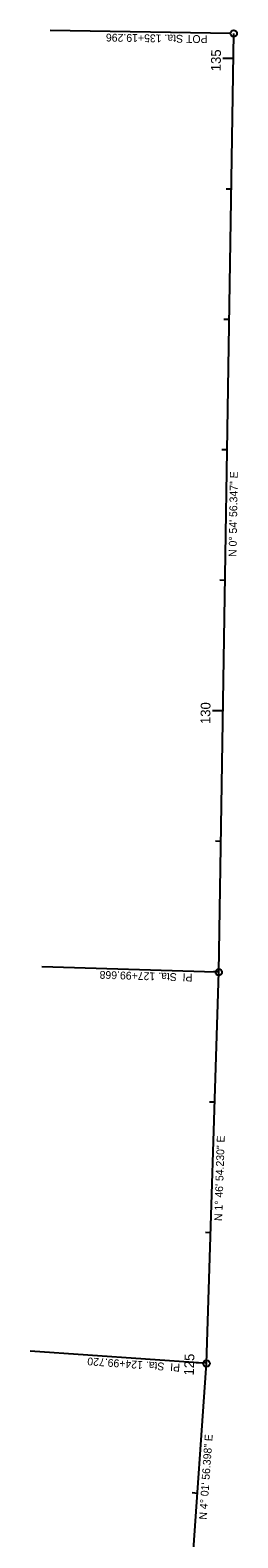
# Model space of a CAD drawing. Extents: x 1384921 to 1386651, y 1973711 to 1976329.
# Drawn here: x 1385069 to 1385228, y 1975173 to 1976329 of the extents above; entities that cross this region are included whole.
import ezdxf

# ---------------------------------------------------------------- set-up
doc = ezdxf.new("R2010")
doc.units = 0
for name, color, linetype in [('S_BREAKLINE', 7, 'Continuous'), ('S_BRIDGE', 7, 'Continuous'), ('S_DRIVEWAY', 7, 'Continuous'), ('S_PAVEMENT_CROWN', 7, 'Continuous'), ('S_SHOULDER', 7, 'Continuous')]:
    doc.layers.add(name, color=color, linetype=linetype)

msp = doc.modelspace()

# ---------------------------------------------------------------- linework, layer by layer
at = {"layer": 'S_BREAKLINE'}
for p, q in [((1385222.8, 1976326.3), (1385084.6, 1976328.5)), ((1385211.3, 1975606.8), (1385078.4, 1975610.9)), ((1385202, 1975307.1), (1385069.4, 1975316.4))]:
    msp.add_line(p, q, dxfattribs=at)
for centre in [(1385225.3, 1976326.2), (1385213.8, 1975606.7), (1385204.5, 1975306.9)]:
    msp.add_circle(centre, 2.5, dxfattribs=at)
at = {"layer": 'S_DRIVEWAY'}
for p, q in [((1385225, 1976306.9), (1385217, 1976307.1)), ((1385223.4, 1976207), (1385219.4, 1976207)), ((1385221.8, 1976107), (1385217.8, 1976107)), ((1385220.2, 1976007), (1385216.2, 1976007)), ((1385218.6, 1975907), (1385214.6, 1975907.1)), ((1385217, 1975807), (1385209, 1975807.1)), ((1385215.4, 1975707), (1385211.4, 1975707.1)), ((1385213.8, 1975607), (1385209.8, 1975607.1)), ((1385210.7, 1975507.1), (1385206.7, 1975507.2)), ((1385207.6, 1975407.1), (1385203.6, 1975407.3)), ((1385204.5, 1975307.2), (1385196.5, 1975307.4)), ((1385197.5, 1975207.4), (1385193.5, 1975207.7))]:
    msp.add_line(p, q, dxfattribs=at)
at = {"layer": 'S_SHOULDER'}
for p, q in [((1385213.8, 1975606.7), (1385225.3, 1976326.2)), ((1385213.8, 1975606.7), (1385225.3, 1976326.2)), ((1385204.5, 1975306.9), (1385213.8, 1975606.7)), ((1385204.5, 1975306.9), (1385213.8, 1975606.7)), ((1385193.4, 1975149.5), (1385204.5, 1975306.9)), ((1385193.4, 1975149.5), (1385204.5, 1975306.9))]:
    msp.add_line(p, q, dxfattribs=at)

# ---------------------------------------------------------------- texts
at = {"layer": 'S_BREAKLINE'}
for s, rotation, p in [('POT Sta. 135+19.296', 179.0843, (1385205.3, 1976324.8)), ('PI  Sta. 127+99.668', 178.2183, (1385193.8, 1975605.6)), ('PI  Sta. 124+99.720', 175.9677, (1385184.4, 1975306.6))]:
    msp.add_text(s, height=6, rotation=rotation, dxfattribs=at).set_placement(p)
at = {"layer": 'S_BRIDGE'}
for s, rotation, p in [('135', 89.0843, (1385215.3, 1976297.2)), ('130', 89.0843, (1385207.3, 1975796.9)), ('125', 88.2183, (1385194.7, 1975297.6))]:
    msp.add_text(s, height=7.5, rotation=rotation, dxfattribs=at).set_placement(p)
at = {"layer": 'S_PAVEMENT_CROWN'}
for s, rotation, p in [('N 0%%d 54\' 56.347" E', 89.0843, (1385227.4, 1975925)), ('N 1%%d 46\' 54.230" E', 88.2183, (1385216.4, 1975416)), ('N 4%%d 01\' 56.398" E', 85.9677, (1385204.6, 1975187.1))]:
    msp.add_text(s, height=6, rotation=rotation, dxfattribs=at).set_placement(p)

doc.saveas('drawing.dxf')
